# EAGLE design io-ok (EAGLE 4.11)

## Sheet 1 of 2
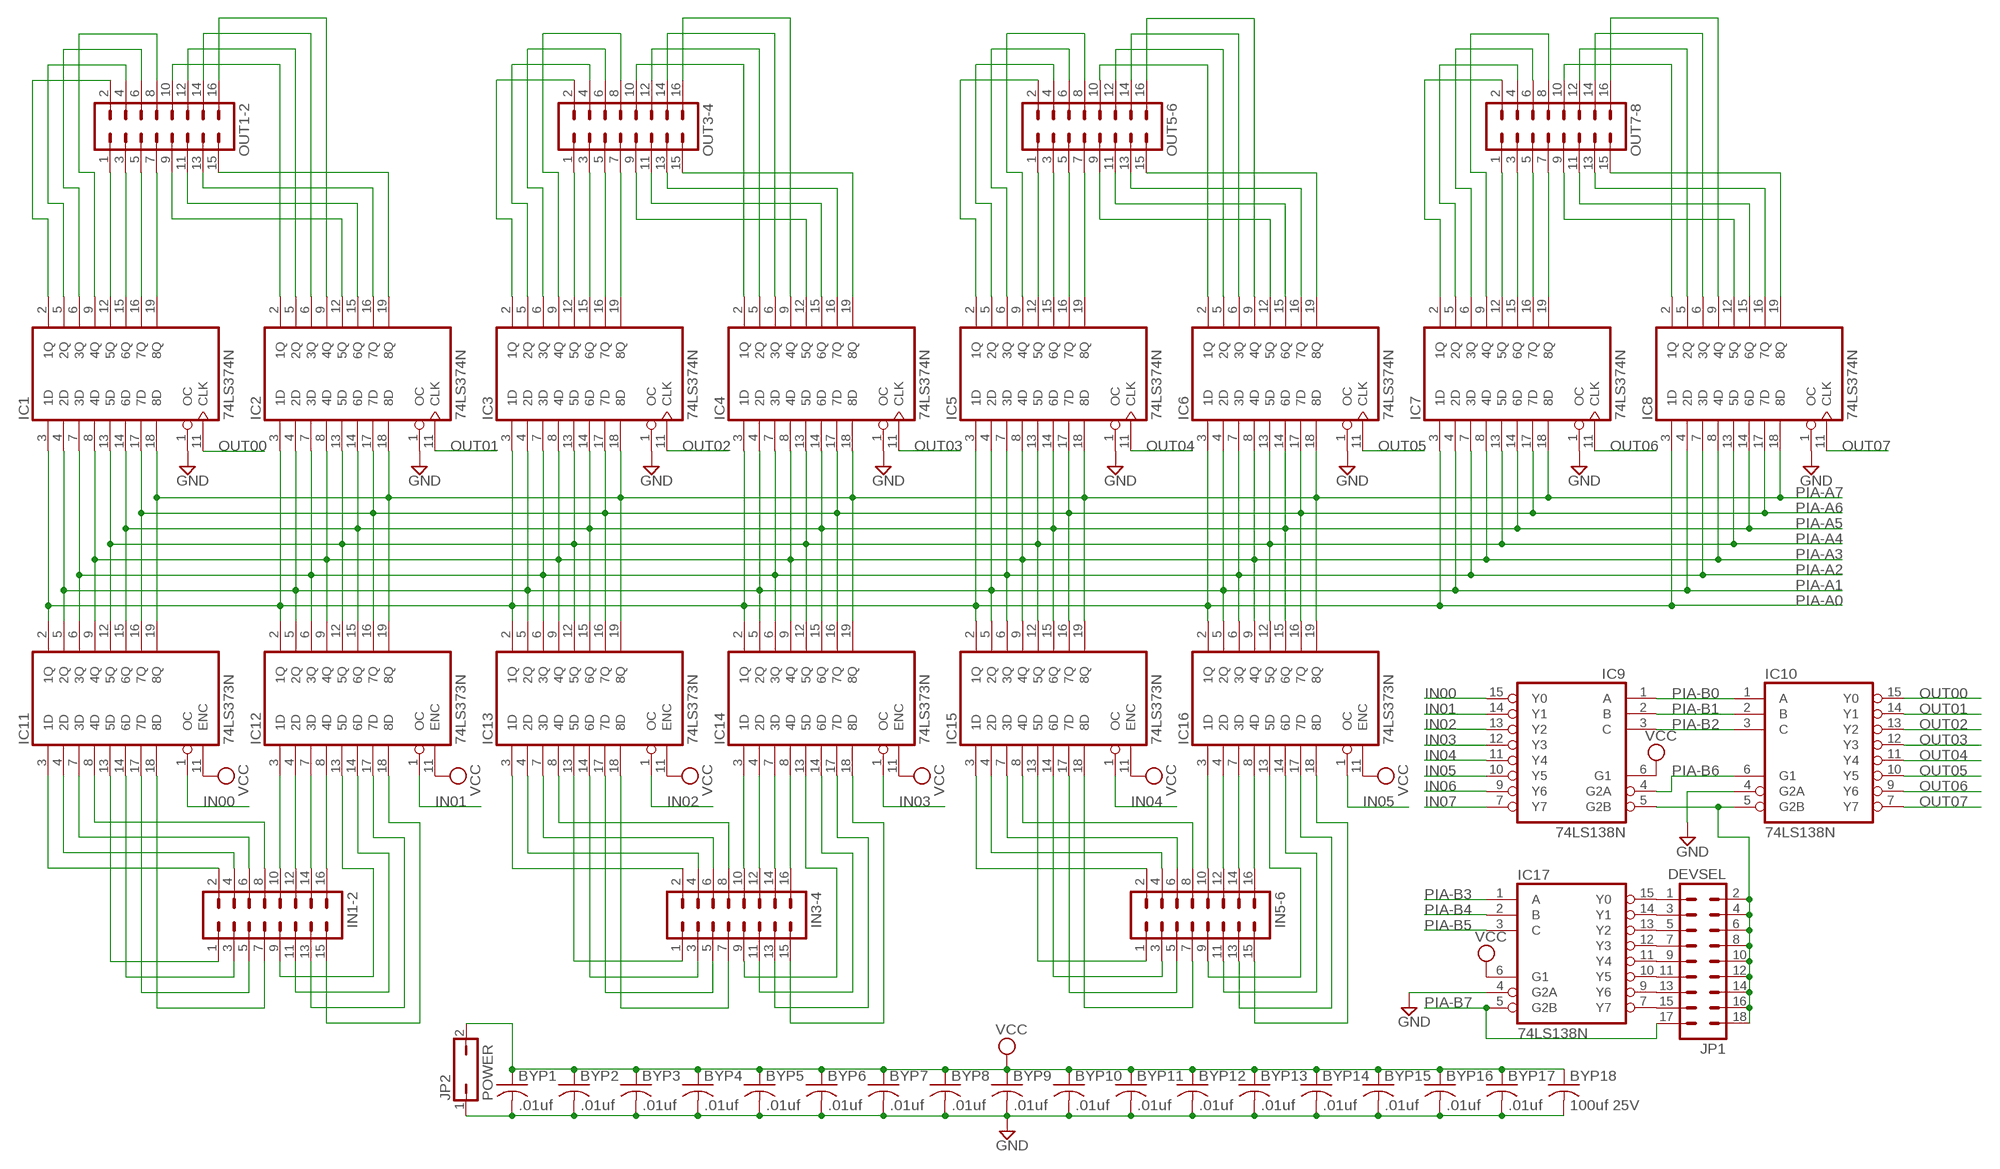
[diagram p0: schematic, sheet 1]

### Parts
BYP1  .01uf  C-US050-025X075  [C050-025X075]
BYP2  .01uf  C-US050-025X075  [C050-025X075]
BYP3  .01uf  C-US050-025X075  [C050-025X075]
BYP4  .01uf  C-US050-025X075  [C050-025X075]
BYP5  .01uf  C-US050-025X075  [C050-025X075]
BYP6  .01uf  C-US050-025X075  [C050-025X075]
BYP7  .01uf  C-US050-025X075  [C050-025X075]
BYP8  .01uf  C-US050-025X075  [C050-025X075]
BYP9  .01uf  C-US050-025X075  [C050-025X075]
BYP10  .01uf  C-US050-025X075  [C050-025X075]
BYP11  .01uf  C-US050-025X075  [C050-025X075]
BYP12  .01uf  C-US050-025X075  [C050-025X075]
BYP13  .01uf  C-US050-025X075  [C050-025X075]
BYP14  .01uf  C-US050-025X075  [C050-025X075]
BYP15  .01uf  C-US050-025X075  [C050-025X075]
BYP16  .01uf  C-US050-025X075  [C050-025X075]
BYP17  .01uf  C-US050-025X075  [C050-025X075]
BYP18  100uf 25V  C-US150-064X183  [C150-064X183]
IC1  74LS374N  [DIL20]
IC2  74LS374N  [DIL20]
IC3  74LS374N  [DIL20]
IC4  74LS374N  [DIL20]
IC5  74LS374N  [DIL20]
IC6  74LS374N  [DIL20]
IC7  74LS374N  [DIL20]
IC8  74LS374N  [DIL20]
IC9  74LS138N  [DIL16]
IC10  74LS138N  [DIL16]
IC11  74LS373N  [DIL20]
IC12  74LS373N  [DIL20]
IC13  74LS373N  [DIL20]
IC14  74LS373N  [DIL20]
IC15  74LS373N  [DIL20]
IC16  74LS373N  [DIL20]
IC17  74LS138N  [DIL16]
IN1-2  MA08-2  [MA08-2]
IN3-4  MA08-2  [MA08-2]
IN5-6  MA08-2  [MA08-2]
JP1  DEVSEL  MA09-2  [MA09-2]
JP2  POWER  JP1Q  [JP1]
OUT1-2  MA08-2  [MA08-2]
OUT3-4  MA08-2  [MA08-2]
OUT5-6  MA08-2  [MA08-2]
OUT7-8  MA08-2  [MA08-2]

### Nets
GND [Power]: BYP1.2 BYP2.2 BYP3.2 BYP4.2 BYP5.2 BYP6.2 BYP7.2 BYP8.2 BYP9.2 BYP10.2 BYP11.2 BYP12.2 BYP13.2 BYP14.2 BYP15.2 BYP16.2 BYP17.2 BYP18.2 IC1.1(OC) IC2.1(OC) IC3.1(OC) IC4.1(OC) IC5.1(OC) IC6.1(OC) IC7.1(OC) IC8.1(OC) IC10.4(G2A) IC17.4(G2A) JP2.1 ; also sheet 2
IN00: IC9.15(Y0) IC11.1(OC)
IN01: IC9.14(Y1) IC12.1(OC)
IN02: IC9.13(Y2) IC13.1(OC)
IN03: IC9.12(Y3) IC14.1(OC)
IN04: IC9.11(Y4) IC15.1(OC)
IN05: IC9.10(Y5) IC16.1(OC)
IN06: IC9.9(Y6)
IN07: IC9.7(Y7)
N$1: IC12.3(1D) IN1-2.10
N$2: IC12.4(2D) IN1-2.12
N$3: IC17.15(Y0) JP1.1
N$4: IC17.14(Y1) JP1.3
N$5: IC17.13(Y2) JP1.5
N$6: IC17.12(Y3) JP1.7
N$7: IC12.7(3D) IN1-2.14
N$8: IC12.8(4D) IN1-2.16
N$9: IC11.8(4D) IN1-2.8
N$10: IC11.7(3D) IN1-2.6
N$11: IC11.4(2D) IN1-2.4
N$12: IC11.3(1D) IN1-2.2
N$13: IC11.13(5D) IN1-2.1
N$14: IC11.14(6D) IN1-2.3
N$15: IC11.17(7D) IN1-2.5
N$16: IC11.18(8D) IN1-2.7
N$17: IC12.13(5D) IN1-2.9
N$18: IC12.14(6D) IN1-2.11
N$19: IC12.17(7D) IN1-2.13
N$20: IC12.18(8D) IN1-2.15
N$21: IC17.11(Y4) JP1.9
N$22: IC17.10(Y5) JP1.11
N$23: IC17.9(Y6) JP1.13
N$24: IC17.7(Y7) JP1.15
N$25: IC9.5(G2B) IC10.5(G2B) JP1.2 JP1.4 JP1.6 JP1.8 JP1.10 JP1.12 JP1.14 JP1.16 JP1.18
N$26: IC5.2(1Q) IC7.2(1Q) OUT5-6.2 OUT7-8.2
N$29: IC14.3(1D) IN3-4.10
N$30: IC14.4(2D) IN3-4.12
N$31: IC14.7(3D) IN3-4.14
N$32: IC14.8(4D) IN3-4.16
N$33: IC3.12(5Q) OUT3-4.1
N$34: IC3.15(6Q) OUT3-4.3
N$35: IC3.16(7Q) OUT3-4.5
N$36: IC3.19(8Q) OUT3-4.7
N$37: IC13.3(1D) IN3-4.2
N$38: IC13.4(2D) IN3-4.4
N$39: IC13.7(3D) IN3-4.6
N$40: IC13.8(4D) IN3-4.8
N$41: IC14.13(5D) IN3-4.9
N$42: IC14.14(6D) IN3-4.11
N$43: IC14.17(7D) IN3-4.13
N$44: IC14.18(8D) IN3-4.15
N$45: IC13.13(5D) IN3-4.1
N$46: IC13.14(6D) IN3-4.3
N$47: IC13.17(7D) IN3-4.5
N$48: IC13.18(8D) IN3-4.7
N$49: IC3.5(2Q) OUT3-4.4
N$50: IC3.6(3Q) OUT3-4.6
N$51: IC3.2(1Q) OUT3-4.2
N$52: IC3.9(4Q) OUT3-4.8
N$53: IC1.12(5Q) OUT1-2.1
N$54: IC1.15(6Q) OUT1-2.3
N$55: IC1.16(7Q) OUT1-2.5
N$56: IC1.19(8Q) OUT1-2.7
N$57: IC1.2(1Q) OUT1-2.2
N$58: IC1.5(2Q) OUT1-2.4
N$59: IC1.6(3Q) OUT1-2.6
N$60: IC1.9(4Q) OUT1-2.8
N$61: IC2.19(8Q) OUT1-2.15
N$62: IC2.16(7Q) OUT1-2.13
N$63: IC2.15(6Q) OUT1-2.11
N$64: IC2.12(5Q) OUT1-2.9
N$65: IC2.2(1Q) OUT1-2.10
N$66: IC2.5(2Q) OUT1-2.12
N$67: IC2.6(3Q) OUT1-2.14
N$68: IC2.9(4Q) OUT1-2.16
N$69: IC4.2(1Q) OUT3-4.10
N$70: IC4.5(2Q) OUT3-4.12
N$71: IC4.6(3Q) OUT3-4.14
N$72: IC4.9(4Q) OUT3-4.16
N$73: IC4.19(8Q) OUT3-4.15
N$74: IC4.16(7Q) OUT3-4.13
N$75: IC4.15(6Q) OUT3-4.11
N$76: IC4.12(5Q) OUT3-4.9
N$77: IC16.3(1D) IN5-6.10
N$78: IC16.4(2D) IN5-6.12
N$79: IC16.7(3D) IN5-6.14
N$80: IC16.8(4D) IN5-6.16
N$81: IC5.12(5Q) OUT5-6.1
N$82: IC5.15(6Q) OUT5-6.3
N$83: IC5.16(7Q) OUT5-6.5
N$84: IC5.19(8Q) OUT5-6.7
N$85: IC7.12(5Q) OUT7-8.1
N$86: IC7.15(6Q) OUT7-8.3
N$87: IC7.16(7Q) OUT7-8.5
N$88: IC7.19(8Q) OUT7-8.7
N$89: IC5.5(2Q) OUT5-6.4
N$90: IC5.6(3Q) OUT5-6.6
N$91: IC5.9(4Q) OUT5-6.8
N$92: IC6.12(5Q) OUT5-6.9
N$93: IC6.15(6Q) OUT5-6.11
N$95: IC6.16(7Q) OUT5-6.13
N$96: IC6.19(8Q) OUT5-6.15
N$97: IC6.2(1Q) OUT5-6.10
N$98: IC6.5(2Q) OUT5-6.12
N$99: IC6.6(3Q) OUT5-6.14
N$100: IC6.9(4Q) OUT5-6.16
N$101: IC15.3(1D) IN5-6.2
N$102: IC15.4(2D) IN5-6.4
N$103: IC15.7(3D) IN5-6.6
N$104: IC15.8(4D) IN5-6.8
N$105: IC16.13(5D) IN5-6.9
N$106: IC16.14(6D) IN5-6.11
N$107: IC16.17(7D) IN5-6.13
N$108: IC16.18(8D) IN5-6.15
N$109: IC15.13(5D) IN5-6.1
N$110: IC15.14(6D) IN5-6.3
N$111: IC15.17(7D) IN5-6.5
N$112: IC15.18(8D) IN5-6.7
N$113: IC8.19(8Q) OUT7-8.15
N$114: IC8.16(7Q) OUT7-8.13
N$115: IC8.15(6Q) OUT7-8.11
N$116: IC8.12(5Q) OUT7-8.9
N$117: IC8.2(1Q) OUT7-8.10
N$118: IC8.5(2Q) OUT7-8.12
N$119: IC8.6(3Q) OUT7-8.14
N$120: IC8.9(4Q) OUT7-8.16
N$121: IC7.9(4Q) OUT7-8.8
N$122: IC7.6(3Q) OUT7-8.6
N$123: IC7.5(2Q) OUT7-8.4
OUT00: IC1.11(CLK) IC10.15(Y0)
OUT01: IC2.11(CLK) IC10.14(Y1)
OUT02: IC3.11(CLK) IC10.13(Y2)
OUT03: IC4.11(CLK) IC10.12(Y3)
OUT04: IC5.11(CLK) IC10.11(Y4)
OUT05: IC6.11(CLK) IC10.10(Y5)
OUT06: IC7.11(CLK) IC10.9(Y6)
OUT07: IC8.11(CLK) IC10.7(Y7)
PIA-A0: IC1.3(1D) IC2.3(1D) IC3.3(1D) IC4.3(1D) IC5.3(1D) IC6.3(1D) IC7.3(1D) IC8.3(1D) IC11.2(1Q) IC12.2(1Q) IC13.2(1Q) IC14.2(1Q) IC15.2(1Q) IC16.2(1Q) ; also sheet 2
PIA-A1: IC1.4(2D) IC2.4(2D) IC3.4(2D) IC4.4(2D) IC5.4(2D) IC6.4(2D) IC7.4(2D) IC8.4(2D) IC11.5(2Q) IC12.5(2Q) IC13.5(2Q) IC14.5(2Q) IC15.5(2Q) IC16.5(2Q) ; also sheet 2
PIA-A2: IC1.7(3D) IC2.7(3D) IC3.7(3D) IC4.7(3D) IC5.7(3D) IC6.7(3D) IC7.7(3D) IC8.7(3D) IC11.6(3Q) IC12.6(3Q) IC13.6(3Q) IC14.6(3Q) IC15.6(3Q) IC16.6(3Q) ; also sheet 2
PIA-A3: IC1.8(4D) IC2.8(4D) IC3.8(4D) IC4.8(4D) IC5.8(4D) IC6.8(4D) IC7.8(4D) IC8.8(4D) IC11.9(4Q) IC12.9(4Q) IC13.9(4Q) IC14.9(4Q) IC15.9(4Q) IC16.9(4Q) ; also sheet 2
PIA-A4: IC1.13(5D) IC2.13(5D) IC3.13(5D) IC4.13(5D) IC5.13(5D) IC6.13(5D) IC7.13(5D) IC8.13(5D) IC11.12(5Q) IC12.12(5Q) IC13.12(5Q) IC14.12(5Q) IC15.12(5Q) IC16.12(5Q) ; also sheet 2
PIA-A5: IC1.14(6D) IC2.14(6D) IC3.14(6D) IC4.14(6D) IC5.14(6D) IC6.14(6D) IC7.14(6D) IC8.14(6D) IC11.15(6Q) IC12.15(6Q) IC13.15(6Q) IC14.15(6Q) IC15.15(6Q) IC16.15(6Q) ; also sheet 2
PIA-A6: IC1.17(7D) IC2.17(7D) IC3.17(7D) IC4.17(7D) IC5.17(7D) IC6.17(7D) IC7.17(7D) IC8.17(7D) IC11.16(7Q) IC12.16(7Q) IC13.16(7Q) IC14.16(7Q) IC15.16(7Q) IC16.16(7Q) ; also sheet 2
PIA-A7: IC1.18(8D) IC2.18(8D) IC3.18(8D) IC4.18(8D) IC5.18(8D) IC6.18(8D) IC7.18(8D) IC8.18(8D) IC11.19(8Q) IC12.19(8Q) IC13.19(8Q) IC14.19(8Q) IC15.19(8Q) IC16.19(8Q) ; also sheet 2
PIA-B0: IC9.1(A) IC10.1(A) ; also sheet 2
PIA-B1: IC9.2(B) IC10.2(B) ; also sheet 2
PIA-B2: IC9.3(C) IC10.3(C) ; also sheet 2
PIA-B3: IC17.1(A) ; also sheet 2
PIA-B4: IC17.2(B) ; also sheet 2
PIA-B5: IC17.3(C) ; also sheet 2
PIA-B6: IC9.4(G2A) IC10.6(G1) ; also sheet 2
PIA-B7: IC17.5(G2B) JP1.17 ; also sheet 2
VCC [Power]: BYP1.1 BYP2.1 BYP3.1 BYP4.1 BYP5.1 BYP6.1 BYP7.1 BYP8.1 BYP9.1 BYP10.1 BYP11.1 BYP12.1 BYP13.1 BYP14.1 BYP15.1 BYP16.1 BYP17.1 BYP18.1 IC9.6(G1) IC11.11(ENC) IC12.11(ENC) IC13.11(ENC) IC14.11(ENC) IC15.11(ENC) IC16.11(ENC) IC17.6(G1) JP2.2 ; also sheet 2

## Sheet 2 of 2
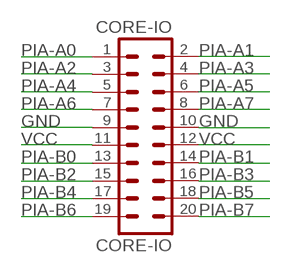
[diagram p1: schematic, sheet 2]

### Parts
CORE-IO  CORE-IO  MA10-2  [MA10-2]

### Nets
GND [Power]: CORE-IO.9 CORE-IO.10 ; also sheet 1
PIA-A0: CORE-IO.1 ; also sheet 1
PIA-A1: CORE-IO.2 ; also sheet 1
PIA-A2: CORE-IO.3 ; also sheet 1
PIA-A3: CORE-IO.4 ; also sheet 1
PIA-A4: CORE-IO.5 ; also sheet 1
PIA-A5: CORE-IO.6 ; also sheet 1
PIA-A6: CORE-IO.7 ; also sheet 1
PIA-A7: CORE-IO.8 ; also sheet 1
PIA-B0: CORE-IO.13 ; also sheet 1
PIA-B1: CORE-IO.14 ; also sheet 1
PIA-B2: CORE-IO.15 ; also sheet 1
PIA-B3: CORE-IO.16 ; also sheet 1
PIA-B4: CORE-IO.17 ; also sheet 1
PIA-B5: CORE-IO.18 ; also sheet 1
PIA-B6: CORE-IO.19 ; also sheet 1
PIA-B7: CORE-IO.20 ; also sheet 1
VCC [Power]: CORE-IO.11 CORE-IO.12 ; also sheet 1

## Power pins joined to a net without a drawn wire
GND: IC1.10(GND) IC2.10(GND) IC3.10(GND) IC4.10(GND) IC5.10(GND) IC6.10(GND) IC7.10(GND) IC8.10(GND) IC9.8(GND) IC10.8(GND) IC11.10(GND) IC12.10(GND) IC13.10(GND) IC14.10(GND) IC15.10(GND) IC16.10(GND) IC17.8(GND)
VCC: IC1.20(VCC) IC2.20(VCC) IC3.20(VCC) IC4.20(VCC) IC5.20(VCC) IC6.20(VCC) IC7.20(VCC) IC8.20(VCC) IC9.16(VCC) IC10.16(VCC) IC11.20(VCC) IC12.20(VCC) IC13.20(VCC) IC14.20(VCC) IC15.20(VCC) IC16.20(VCC) IC17.16(VCC)

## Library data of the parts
BYP1-BYP18 = rcl:C-US: CAPACITOR, American symbol
CORE-IO = con-lstb:MA10-2: PIN HEADER
IC1-IC8 = 74xx-us:74*374: Octal D type transparent LATCH, edge triggered
IC9 IC10 IC17 = 74xx-us:74*138: 3-line to 8-line DECODER/DEMULTIPLEXER
IC11-IC16 = 74xx-us:74*373: Octal D type transparent LATCH, edge triggered
IN1-2 IN3-4 IN5-6 OUT1-2 OUT3-4 OUT5-6 OUT7-8 = con-lstb:MA08-2: PIN HEADER
JP1 = con-lstb:MA09-2: PIN HEADER
JP2 = jumper:JP1Q: JUMPER

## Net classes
1 Power: width 0.508 mm, drill 0.254 mm, clearance 0.254 mm

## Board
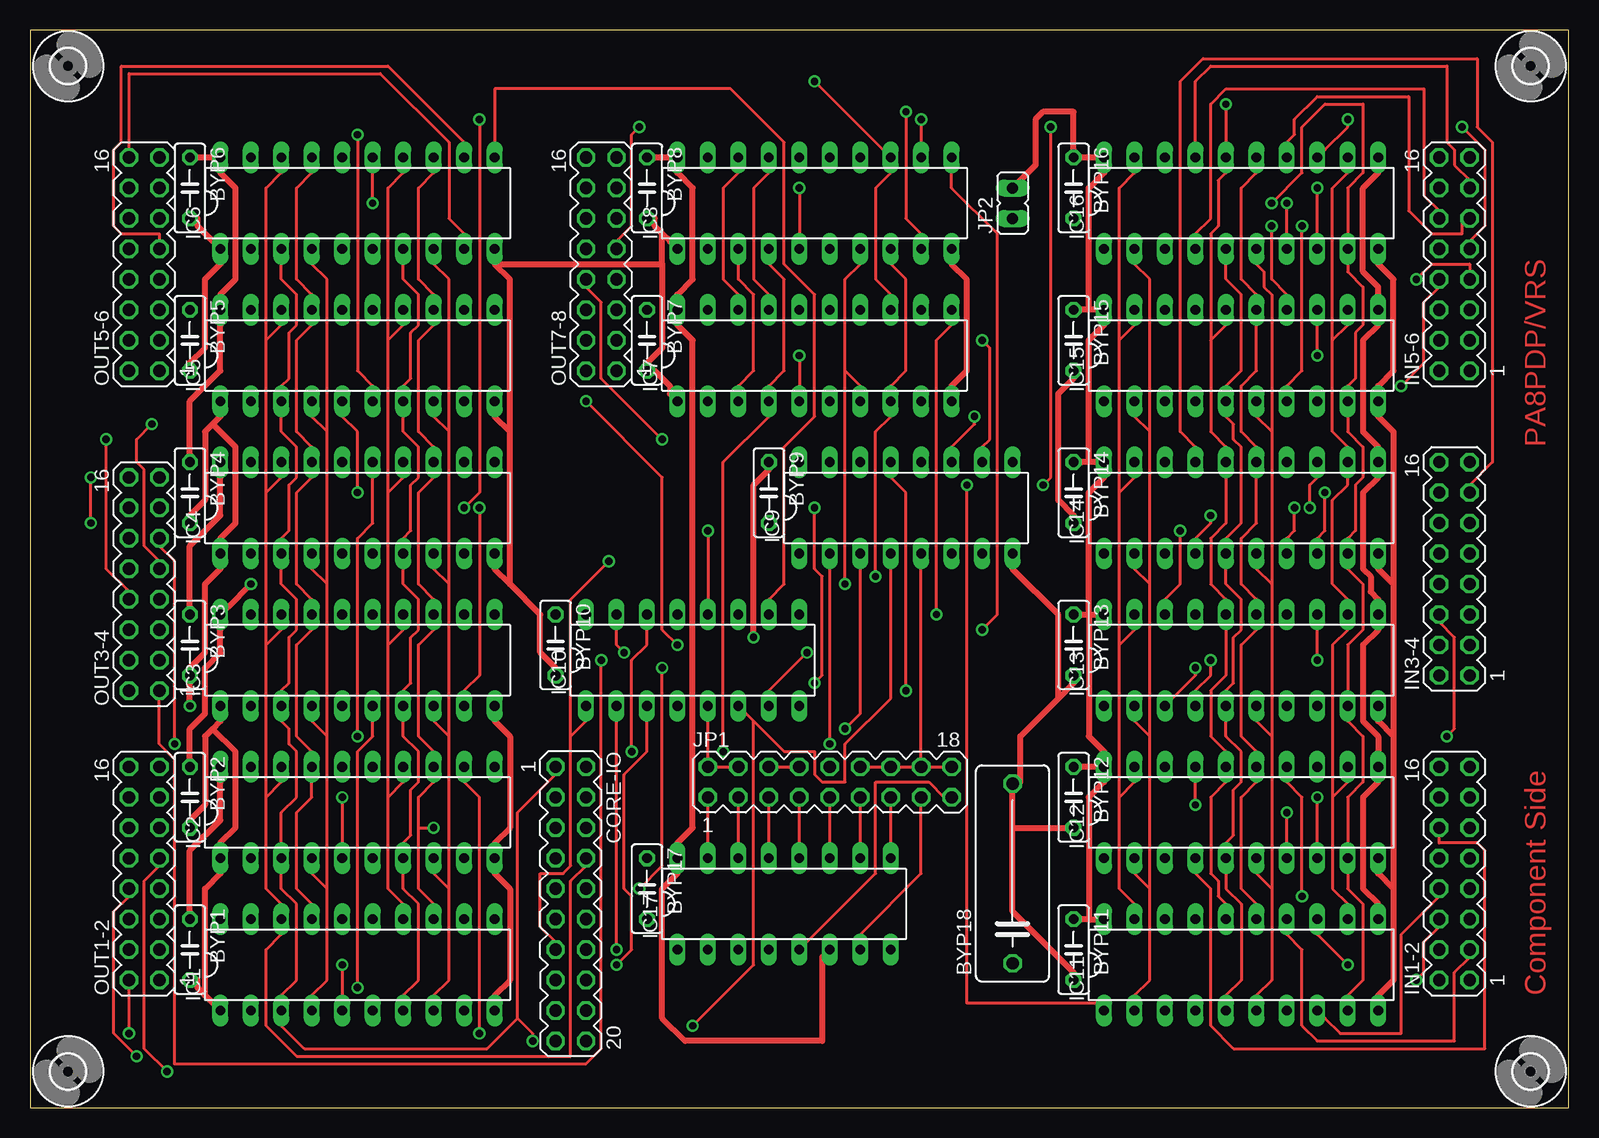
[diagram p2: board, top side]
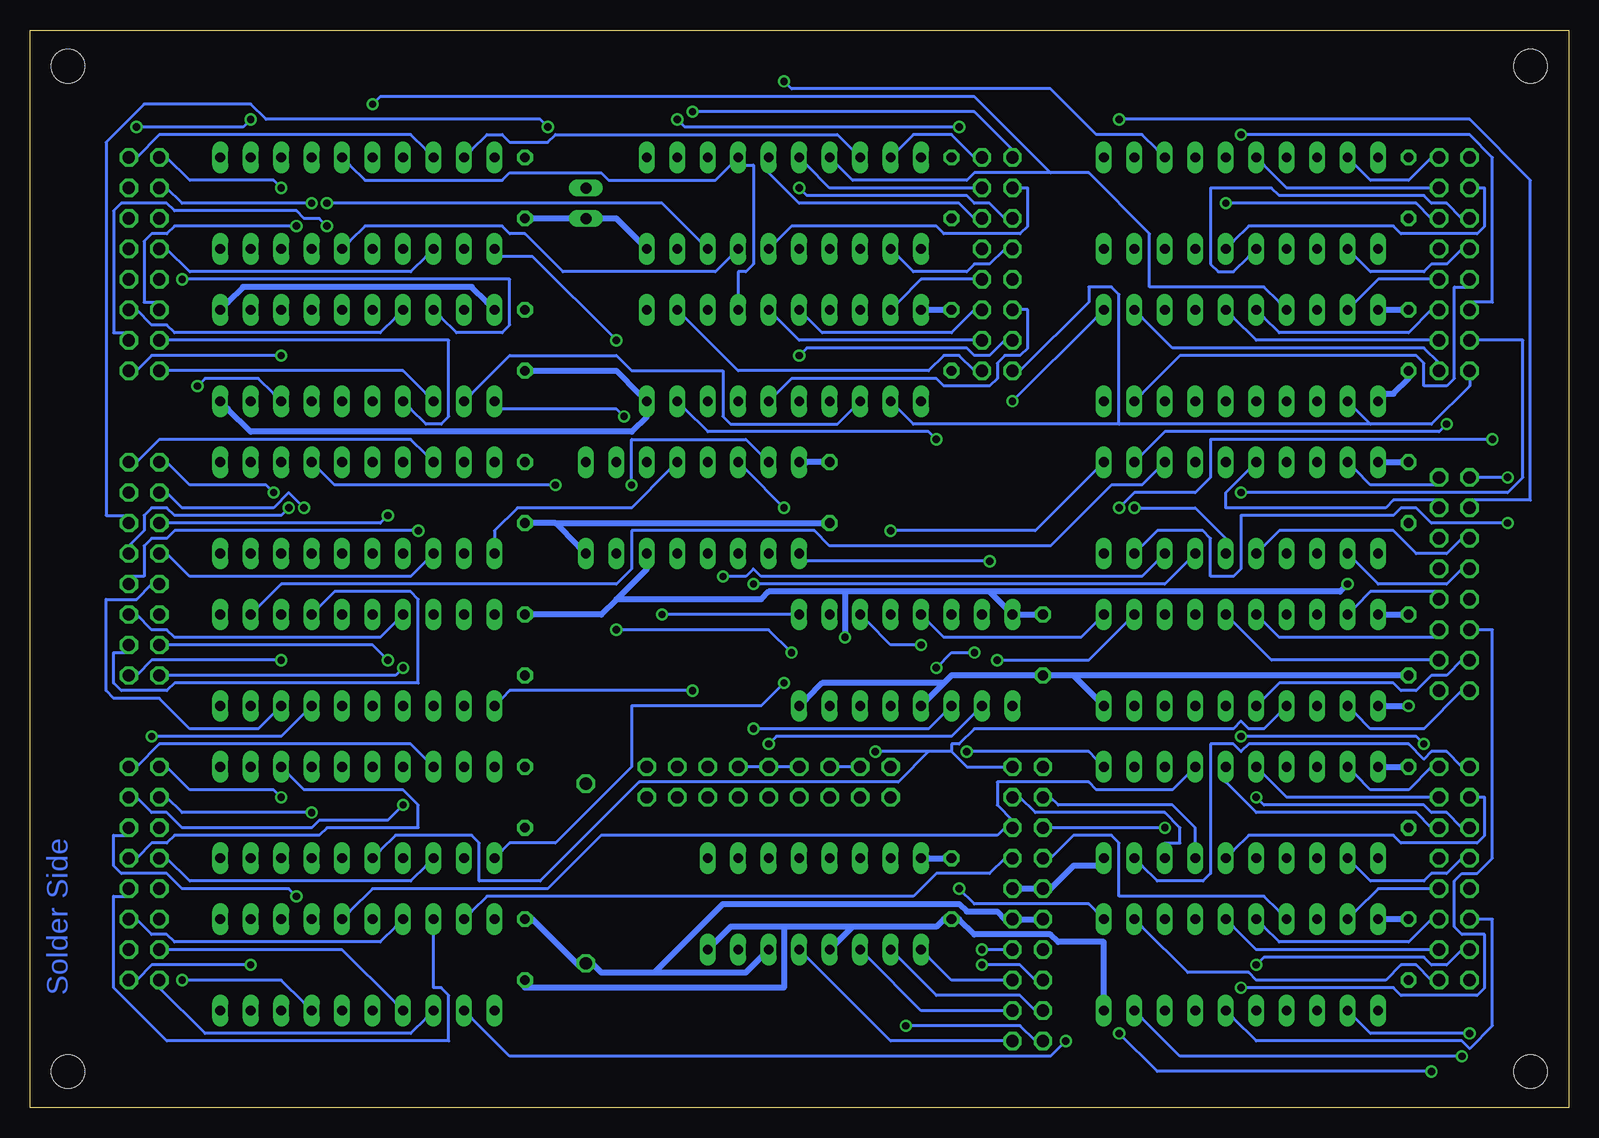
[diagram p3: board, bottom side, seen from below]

Size 128.25 x 89.84 mm. Coordinates in mm from the lower left corner, seen from the top.
Outline: 0,0 128.25,0 128.25,89.84 0,89.84 0,0
Copper layers (1*16): Top 0.035mm / dielectric 1.5mm / Bottom 0.035mm
Design rules "olimex10mil": minimum track width 10mil, minimum drill 24mil, track to track 10mil, track to pad 10mil, pad to pad 10mil, via to via 10mil, smd to smd 10mil, copper to edge 40mil, drill to drill 10mil, minimum pad ring 10mil, minimum via ring 8mil, stop-mask expansion 0mil, vias tented up to drill 0mil, thermal gap 10mil

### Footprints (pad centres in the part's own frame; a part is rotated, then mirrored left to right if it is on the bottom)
C050-025X075 = drill 0.813 octagon: 1 -2.54,0; 2 2.54,0
C150-064X183 = drill 1.016 octagon: 1 -7.493,0; 2 7.493,0
MA10-2 = drill 1.016 octagon: 1 -11.43,-1.27; 2 -11.43,1.27; 3 -8.89,-1.27; 4 -8.89,1.27; 5 -6.35,-1.27; 6 -6.35,1.27; 7 -3.81,-1.27; 8 -3.81,1.27; 9 -1.27,-1.27; 10 -1.27,1.27; 11 1.27,-1.27; 12 1.27,1.27; 13 3.81,-1.27; 14 3.81,1.27; 15 6.35,-1.27; 16 6.35,1.27; 17 8.89,-1.27; 18 8.89,1.27; 19 11.43,-1.27; 20 11.43,1.27
DIL20 = drill 0.813 long: 1 -11.43,-3.81; 2 -8.89,-3.81; 3 -6.35,-3.81; 4 -3.81,-3.81; 5 -1.27,-3.81; 6 1.27,-3.81; 7 3.81,-3.81; 8 6.35,-3.81; 9 8.89,-3.81; 10 11.43,-3.81; 11 11.43,3.81; 12 8.89,3.81; 13 6.35,3.81; 14 3.81,3.81; 15 1.27,3.81; 16 -1.27,3.81; 17 -3.81,3.81; 18 -6.35,3.81; 19 -8.89,3.81; 20 -11.43,3.81
DIL16 = drill 0.813 long: 1 -8.89,-3.81; 2 -6.35,-3.81; 3 -3.81,-3.81; 4 -1.27,-3.81; 5 1.27,-3.81; 6 3.81,-3.81; 7 6.35,-3.81; 8 8.89,-3.81; 9 8.89,3.81; 10 6.35,3.81; 11 3.81,3.81; 12 1.27,3.81; 13 -1.27,3.81; 14 -3.81,3.81; 15 -6.35,3.81; 16 -8.89,3.81
MA08-2 = drill 1.016 octagon: 1 -8.89,-1.27; 2 -8.89,1.27; 3 -6.35,-1.27; 4 -6.35,1.27; 5 -3.81,-1.27; 6 -3.81,1.27; 7 -1.27,-1.27; 8 -1.27,1.27; 9 1.27,-1.27; 10 1.27,1.27; 11 3.81,-1.27; 12 3.81,1.27; 13 6.35,-1.27; 14 6.35,1.27; 15 8.89,-1.27; 16 8.89,1.27
MA09-2 = drill 1.016 octagon: 1 -10.16,-1.27; 2 -10.16,1.27; 3 -7.62,-1.27; 4 -7.62,1.27; 5 -5.08,-1.27; 6 -5.08,1.27; 7 -2.54,-1.27; 8 -2.54,1.27; 9 0,-1.27; 10 0,1.27; 11 2.54,-1.27; 12 2.54,1.27; 13 5.08,-1.27; 14 5.08,1.27; 15 7.62,-1.27; 16 7.62,1.27; 17 10.16,-1.27; 18 10.16,1.27
JP1 = drill 0.914 long: 1 0,-1.27; 2 0,1.27
2,8 = hole 2.8: 0,0

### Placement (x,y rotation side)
BYP1  13.33,13.17 270 top
BYP2  13.33,25.87 270 top
BYP3  13.33,38.57 270 top
BYP4  13.33,51.27 270 top
BYP5  13.33,63.97 270 top
BYP6  13.33,76.67 270 top
BYP7  51.43,63.97 270 top
BYP8  51.43,76.67 270 top
BYP9  61.59,51.27 270 top
BYP10  43.81,38.57 270 top
BYP11  86.99,13.17 270 top
BYP12  86.99,25.87 270 top
BYP13  86.99,38.57 270 top
BYP14  86.99,51.27 270 top
BYP15  86.99,63.97 270 top
BYP16  86.99,76.67 270 top
BYP17  51.43,18.25 270 top
BYP18  81.91,19.52 90 top
CORE-IO  45.08,16.98 270 top
IC1  27.3,11.9 0 top
IC2  27.3,24.6 0 top
IC3  27.3,37.3 0 top
IC4  27.3,50 0 top
IC5  27.3,62.7 0 top
IC6  27.3,75.4 0 top
IC7  65.4,62.7 0 top
IC8  65.4,75.4 0 top
IC9  73.02,50 0 top
IC10  55.24,37.3 0 top
IC11  100.96,11.9 0 top
IC12  100.96,24.6 0 top
IC13  100.96,37.3 0 top
IC14  100.96,50 0 top
IC15  100.96,62.7 0 top
IC16  100.96,75.4 0 top
IC17  62.86,16.98 0 top
IN1-2  118.74,19.52 90 top
IN3-4  118.74,44.92 90 top
IN5-6  118.74,70.32 90 top
JP1  66.67,27.14 0 top
JP2  81.91,75.4 0 top
OUT1-2  9.52,19.52 90 top
OUT3-4  9.52,43.65 90 top
OUT5-6  9.52,70.32 90 top
OUT7-8  47.62,70.32 90 top
U$1  [2,8]  125.09,3.01 0 top
U$2  [2,8]  125.09,86.83 0 top
U$3  [2,8]  3.17,86.83 0 top
U$4  [2,8]  3.17,3.01 0 top

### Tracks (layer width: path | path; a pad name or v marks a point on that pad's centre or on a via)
GND  (via drill 0.61)
  Top 0.508: 15.24,31.58 15.87,32.22 IC3.1 | 15.24,31.58 14.6,30.95 14.6,25.23 13.33,23.96 BYP2.2 | 14.6,9.36 13.97,10 13.97,10.63 BYP1.2 | 14.6,9.36 15.24,8.73 IC1.1 | 14.6,9.36 14.6,18.25 15.87,19.52 IC2.1 15.87,22.06 17.14,23.33 17.14,29.68 15.24,31.58 | BYP6.2 13.97,74.13 13.97,73.5 15.24,72.22 IC6.1 15.87,70.32 14.6,69.05 14.6,63.34 13.33,62.06 BYP5.2 | 15.24,56.98 15.87,57.62 IC5.1 | 15.24,56.98 14.6,56.35 14.6,50.63 13.33,49.37 BYP4.2 | 15.24,56.98 17.14,55.08 17.14,48.73 15.87,47.46 IC4.1 15.87,44.92 14.6,43.65 14.6,37.94 13.33,36.66 BYP3.2 13.33,35.39 v13.33,33.49 | IC1.10 38.73,9.36 40,10.63 40,18.25 38.73,19.52 IC2.10 38.73,22.06 40,23.33 40,30.95 38.73,32.22 IC3.10 | IC7.1 53.34,59.52 53.34,60.16 52.07,61.43 BYP7.2 51.43,62.06 52.7,63.34 52.7,70.32 | 52.7,72.86 52.07,73.5 52.07,74.13 BYP8.2 | 52.7,72.86 53.34,72.22 IC8.1 | 52.7,70.32 52.7,72.86 | 40,43.65 42.54,41.11 42.54,37.94 43.81,36.66 BYP10.2 | 40,43.65 38.73,44.92 IC4.10 | 40,56.35 38.73,57.62 IC5.10 | 40,43.65 40,56.35 | 38.73,70.32 40,69.05 40,56.35 | 38.73,70.32 IC6.10 38.73,70.32 | 38.73,70.32 52.7,70.32 | 113.66,18.25 113.66,10.63 112.39,9.36 IC11.10 | 113.66,18.25 112.39,19.52 IC12.10 | 113.66,30.95 112.39,32.22 IC13.10 | 113.66,30.95 113.66,18.25 | 113.66,43.65 112.39,44.92 IC14.10 | 113.66,43.65 113.66,30.95 | 113.66,43.65 113.66,56.35 112.39,57.62 IC15.10 112.39,60.16 113.66,61.43 113.66,69.05 112.39,70.32 IC16.10 | IC7.10 76.83,60.16 78.1,61.43 78.1,69.05 76.83,70.32 IC8.10 | BYP15.2 86.99,60.8 85.72,59.52 85.72,50.63 86.99,49.37 BYP14.2 | 81.91,23.33 81.91,26.5 BYP18.2 82.55,27.14 82.55,30.95 85.72,34.12
  Top 0.508: 81.91,23.33 81.91,16.34 86.99,11.27 BYP11.2 | 81.91,23.33 86.35,23.33 BYP12.2 | 85.72,34.12 86.99,35.39 BYP13.2 | 85.72,34.12 85.72,41.11 81.91,44.92 IC9.8
  Bottom 0.508: BYP5.2 13.33,60.8 14.6,59.52 15.24,59.52 IC5.1 | v13.33,33.49 15.24,33.49 IC3.1 | CORE-IO.10 45.72,18.25 44.45,18.25 CORE-IO.9 43.18,18.25 41.27,20.15 39.37,20.15 IC2.10 | 41.27,36.03 39.37,34.12 IC3.10 | 41.27,36.03 43.18,36.03 BYP10.2 44.45,36.03 51.43,36.03 52.07,35.39 | 52.07,35.39 53.34,34.12 IC10.4 | 52.07,35.39 62.23,35.39 63.5,34.12 IC10.8 | 41.27,36.03 13.97,36.03 BYP3.2 | BYP15.2 86.35,61.43 79.37,61.43 77.46,59.52 IC7.10 76.83,57.62 78.1,56.35 109.85,56.35 111.75,58.25 IC15.10 | IC8.10 77.46,72.22 79.37,74.13 80.64,74.13 JP2.1 83.18,74.13 86.35,74.13 BYP16.2 | 84.45,48.73 82.55,46.82 IC9.8 | 84.45,48.73 86.35,48.73 BYP14.2 | 84.45,48.73 62.23,48.73 BYP9.2 | 59.69,15.08 52.7,15.08 52.07,15.71 BYP17.2 50.8,15.71 49.53,14.44 43.18,14.44 42.54,13.81 38.73,13.81 38.73,9.36 IC1.10 | 59.69,15.08 60.96,13.81 IC17.4 | 59.69,15.08 65.4,15.08 | 65.4,15.08 69.84,15.08 71.11,13.81 IC17.8 | 65.4,15.08 65.4,10 86.99,10 BYP11.2
IN00  (via drill 0.61)
  Top 0.254: v78.1,51.91 78.1,8.73 88.89,8.73 IC11.1
  Bottom 0.254: v78.1,51.91 78.1,55.71 68.57,55.71 67.3,54.45 IC9.15
IN01  (via drill 0.61)
  Top 0.254: v65.4,35.39 66.03,36.03 66.03,44.28 65.4,44.92 v65.4,50
  Bottom 0.254: v65.4,35.39 67.3,33.49 78.1,33.49 78.1,28.41 84.45,22.06 88.26,22.06 88.89,21.42 IC12.1 | v65.4,50 68.57,53.17 IC9.14
IN02  (via drill 0.61)
  Top 0.254: v73.02,34.76 73.02,51.27 71.75,52.54 IC9.13
  Bottom 0.254: v73.02,34.76 88.26,34.76 88.89,34.12 IC13.1
IN03
  Bottom 0.254: IC9.12 74.92,53.17 78.1,50 87.62,50 89.53,48.09 89.53,47.46 IC14.1
IN04  (via drill 0.61)
  Top 0.254: v78.73,57.62 78.73,56.98 76.83,55.08 IC9.11
  Bottom 0.254: v78.73,57.62 79.37,58.25 88.89,58.25 IC15.1
IN05  (via drill 0.61)
  Top 0.254: v79.37,63.97 80,63.34 80,55.71 79.37,55.08 IC9.10
  Bottom 0.254: v79.37,63.97 86.35,70.95 88.89,70.95 IC16.1
N$1
  Bottom 0.254: IC12.3 95.24,20.15 96.52,18.88 114.93,18.88 116.83,20.79 IN1-2.10
N$2
  Top 0.254: IC12.4 97.15,19.52 98.42,18.25 98.42,6.82 100.32,4.92 121.28,4.92 121.28,21.42 120.64,22.06 117.47,22.06 117.47,22.7 IN1-2.12
N$3
  Top 0.254: IC17.15 56.51,22.06 56.51,25.23 JP1.1
N$4
  Top 0.254: IC17.14 59.05,22.06 59.05,25.23 JP1.3
N$5
  Top 0.254: IC17.13 61.59,22.06 61.59,25.23 JP1.5
N$6
  Top 0.254: IC17.12 64.13,22.06 64.13,25.23 JP1.7
N$7  (via drill 0.61)
  Top 0.254: v104.77,24.6 104.77,22.06 IC12.7
  Bottom 0.254: v104.77,24.6 115.56,24.6 116.83,25.87 IN1-2.14
N$8  (via drill 0.61)
  Top 0.254: v107.31,25.87 107.31,22.06 IC12.8
  Bottom 0.254: v107.31,25.87 107.94,26.5 114.93,26.5 116.83,28.41 IN1-2.16
N$9
  Top 0.254: IC11.8 107.94,7.46 109.21,6.18 114.3,6.18 114.3,14.44 117.47,17.61 IN1-2.8
N$10  (via drill 0.61)
  Top 0.254: v115.56,10.63 116.2,11.27 116.2,13.81 117.47,15.08 IN1-2.6
  Bottom 0.254: v115.56,10.63 107.31,10.63 105.41,8.73 IC11.7
N$11
  Bottom 0.254: IC11.4 97.78,8.73 102.23,13.17 116.83,13.17 IN1-2.4
N$12
  Bottom 0.254: IC11.3 95.24,7.46 96.52,6.18 113.66,6.18 117.47,10 IN1-2.2
N$13  (via drill 0.61)
  Top 0.254: v109.85,11.9 107.31,14.44 IC11.13
  Bottom 0.254: v109.85,11.9 118.1,11.9 119.38,10.63 IN1-2.1
N$14
  Top 0.254: IC11.14 104.77,14.44 106.04,13.17 106.04,6.82 107.31,5.55 118.74,5.55 118.74,11.27 120.01,12.54 IN1-2.3
N$15
  Bottom 0.254: IC11.17 97.78,15.08 99.05,13.81 116.2,13.81 116.83,14.44 118.1,14.44 119.38,15.71 IN1-2.5
N$16
  Bottom 0.254: IC11.18 94.61,14.44 94.61,10 93.97,10 93.34,9.36 93.34,5.55 116.83,5.55 121.28,10 121.28,17.61 120.01,17.61 IN1-2.7
N$17
  Bottom 0.254: IC12.13 106.67,27.77 105.41,26.5 97.15,26.5 95.88,25.23 95.88,23.33 103.5,23.33 104.13,22.7 116.2,22.7 116.83,22.06 118.1,22.06 119.38,20.79 IN1-2.9
N$18  (via drill 0.61)
  Top 0.254: v106.04,17.61 106.04,25.87 104.77,27.14 IC12.14
  Bottom 0.254: v106.04,17.61 106.67,18.25 115.56,18.25 116.83,19.52 120.64,19.52 121.28,20.15 121.28,22.7 120.01,22.7 IN1-2.11
N$19  (via drill 0.61)
  Top 0.254: v97.15,25.23 97.15,27.14 IC12.17
  Bottom 0.254: v97.15,25.23 98.42,23.96 104.13,23.96 104.77,23.33 115.56,23.33 116.83,24.6 118.1,24.6 119.38,25.87 IN1-2.13
N$20
  Bottom 0.254: IC12.18 95.24,29.04 96.52,30.31 117.47,30.31 119.38,28.41 IN1-2.15
N$21
  Top 0.254: IC17.11 66.67,22.06 66.67,25.23 JP1.9
N$22
  Top 0.254: IC17.10 69.21,22.06 69.21,25.23 JP1.11
N$23
  Top 0.254: IC17.9 71.75,22.06 71.75,25.23 JP1.13
N$24
  Top 0.254: IC17.7 69.21,14.44 74.29,19.52 74.29,25.23 JP1.15
N$25
  Top 0.254: IC10.5 56.51,32.22 56.51,29.04 JP1.2 57.15,28.41 58.41,28.41 JP1.4 | JP1.8 63.5,28.41 62.23,28.41 JP1.6 | JP1.12 69.84,28.41 71.11,28.41 JP1.14 72.38,28.41 73.66,28.41 JP1.16 | IC9.5 74.29,44.92 74.29,29.04 JP1.16 | JP1.18 76.19,28.41 74.92,28.41 JP1.16
  Bottom 0.254: JP1.6 60.96,28.41 59.69,28.41 JP1.4 | JP1.8 64.77,28.41 66.03,28.41 JP1.10 67.3,28.41 68.57,28.41 JP1.12
N$26
  Bottom 0.254: 16.5,56.98 17.77,58.25 IC5.2 | 16.5,56.98 11.43,56.98 8.25,60.16 8.25,60.8 OUT5-6.2 | 16.5,56.98 37.46,56.98 | 37.46,56.98 54.61,56.98 55.88,58.25 IC7.2 | 37.46,56.98 37.46,67.78 38.1,68.41 40,68.41 40,67.14 45.72,61.43 OUT7-8.2
N$29
  Bottom 0.254: IC14.3 95.24,45.55 96.52,44.28 114.93,44.28 116.83,46.19 IN3-4.10
N$30  (via drill 0.61)
  Top 0.254: v98.42,49.37 98.42,48.73 97.15,47.46 IC14.4
  Bottom 0.254: v98.42,49.37 99.05,48.73 116.83,48.73 IN3-4.12
N$31  (via drill 0.61)
  Top 0.254: v105.41,50 105.41,48.09 104.77,47.46 IC14.7
  Bottom 0.254: v105.41,50 106.67,51.27 107.94,50 115.56,50 116.83,51.27 IN3-4.14
N$32  (via drill 0.61)
  Top 0.254: v107.94,51.27 107.94,48.09 107.31,47.46 IC14.8
  Bottom 0.254: v107.94,51.27 108.58,51.91 114.93,51.91 116.83,53.81 IN3-4.16
N$33  (via drill 0.61)
  Top 0.254: v47.62,37.3 47.62,4.92 46.35,3.64 12.06,3.64 12.06,29.04 10.79,30.31 10.79,34.12 OUT3-4.1
  Bottom 0.254: v47.62,37.3 40,37.3 36.83,40.48 IC3.12
N$34
  Bottom 0.254: IC3.15 27.93,40.48 24.76,37.3 11.43,37.3 OUT3-4.3
N$35
  Bottom 0.254: IC3.16 25.39,40.48 24.12,39.2 10.79,39.2 OUT3-4.5
N$36
  Bottom 0.254: IC3.19 17.77,41.74 16.5,43.02 10.79,43.02 OUT3-4.7
N$37  (via drill 0.61)
  Top 0.254: v97.15,36.66 97.15,36.03 95.24,34.12 IC13.3
  Bottom 0.254: v97.15,36.66 97.78,36.03 116.83,36.03 IN3-4.2
N$38  (via drill 0.61)
  Top 0.254: v98.42,37.3 98.42,36.03 97.15,34.76 IC13.4
  Bottom 0.254: v98.42,37.3 99.69,38.57 116.83,38.57 IN3-4.4
N$39  (via drill 0.61)
  Top 0.254: v118.1,30.95 118.74,31.58 118.74,39.2 117.47,40.48 IN3-4.6
  Bottom 0.254: v118.1,30.95 107.31,30.95 105.41,32.85 IC13.7
N$40
  Bottom 0.254: IC13.8 107.94,32.85 109.21,31.58 114.93,31.58 117.47,34.12 121.28,34.12 121.91,34.76 121.91,42.38 119.38,42.38 118.1,43.65 IN3-4.8
N$41  (via drill 0.61)
  Top 0.254: v106.67,50 106.67,51.91 107.31,52.54 IC14.13
  Bottom 0.254: v106.67,50 107.31,49.37 116.2,49.37 116.83,50 118.1,50 118.74,49.37 118.74,48.09 120.01,46.82 IN3-4.9
N$42  (via drill 0.61)
  Top 0.254: v84.45,51.91 85.08,52.54 v85.08,81.75
  Bottom 0.254: v84.45,51.91 102.86,51.91 104.13,53.17 IC14.14 | v85.08,81.75 85.72,82.39 108.58,82.39 109.85,83.66 118.74,83.66 121.91,80.48 121.91,49.37 120.01,49.37 IN3-4.11
N$43
  Top 0.254: IC14.17 97.15,55.08 95.88,56.35 95.88,85.56 97.78,87.47 120.64,87.47 120.64,81.75 121.91,80.48 121.91,53.81 120.01,51.91 IN3-4.13
N$44
  Bottom 0.254: IC14.18 95.24,54.45 96.52,55.71 117.47,55.71 119.38,53.81 IN3-4.15
N$45  (via drill 0.61)
  Top 0.254: v107.31,37.3 107.31,39.84 IC13.13
  Bottom 0.254: v107.31,37.3 118.1,37.3 119.38,36.03 IN3-4.1
N$46
  Bottom 0.254: IC13.14 104.13,41.74 102.86,43.02 96.52,43.02 95.88,42.38 95.88,35.39 116.2,35.39 116.83,34.76 120.64,34.76 121.28,35.39 121.28,37.94 120.01,37.94 IN3-4.3
N$47
  Bottom 0.254: IC13.17 97.78,40.48 99.05,39.2 116.2,39.2 116.83,39.84 118.1,39.84 119.38,41.11 IN3-4.5
N$48  (via drill 0.61)
  Top 0.254: v95.88,48.09 95.88,43.65 94.61,42.38 IC13.18
  Bottom 0.254: v95.88,48.09 116.2,48.09 116.83,47.46 118.1,47.46 118.74,46.82 118.74,44.28 120.01,44.28 IN3-4.7
N$49
  Bottom 0.254: IC3.5 25.39,34.12 24.12,35.39 14.6,35.39 13.97,34.76 12.7,34.76 11.43,36.03 10.16,36.03 8.89,37.3 OUT3-4.4
N$50  (via drill 0.61)
  Top 0.254: v27.3,10 27.3,29.68 28.57,30.95 28.57,32.22 IC3.6
  Bottom 0.254: v27.3,10 14.6,10 13.97,9.36 7.62,9.36 6.98,10 6.98,14.44 8.89,14.44 9.52,15.08 9.52,18.88 8.89,19.52 7.62,19.52 6.34,20.79 6.34,39.84 7.62,39.84 OUT3-4.6
N$51
  Bottom 0.254: IC3.2 17.77,32.85 16.5,31.58 12.06,31.58 8.89,34.76 OUT3-4.2
N$52  (via drill 0.61)
  Top 0.254: v37.46,50 37.46,36.03 36.19,34.76 IC3.9 | v6.34,55.71 6.34,44.92 8.25,43.02 OUT3-4.8
  Bottom 0.254: v37.46,50 36.19,51.27 31.11,51.27 29.84,52.54 29.84,55.71 v6.34,55.71
N$53
  Bottom 0.254: IC1.12 35.55,15.08 31.74,11.27 26.66,11.27 26.03,10.63 15.24,10.63 13.97,11.9 12.7,11.9 11.43,10.63 OUT1-2.1
N$54
  Bottom 0.254: IC1.15 27.93,15.08 26.03,13.17 11.43,13.17 OUT1-2.3
N$55
  Bottom 0.254: IC1.16 25.39,15.08 24.12,13.81 13.33,13.81 11.43,15.71 OUT1-2.5
N$56
  Bottom 0.254: IC1.19 17.77,16.34 15.87,18.25 11.43,18.25 OUT1-2.7
N$57  (via drill 0.61)
  Top 0.254: v8.25,6.18 8.25,10 OUT1-2.2
  Bottom 0.254: v8.25,6.18 16.5,6.18 17.77,7.46 IC1.2
N$58  (via drill 0.61)
  Top 0.254: v26.03,11.9 26.03,9.36 IC1.5
  Bottom 0.254: v26.03,11.9 25.39,12.54 12.06,12.54 11.43,11.9 10.16,11.9 8.89,13.17 OUT1-2.4
N$59
  Bottom 0.254: IC1.6 27.93,7.46 26.03,5.55 8.89,5.55 8.25,4.92 6.34,6.82 6.34,15.71 7.62,15.71 OUT1-2.6
N$60  (via drill 0.61)
  Top 0.254: v8.89,4.28 6.98,6.18 6.98,16.34 8.25,17.61 OUT1-2.8
  Bottom 0.254: v8.89,4.28 32.38,4.28 35.55,7.46 IC1.9
N$61
  Bottom 0.254: IC2.19 17.77,27.77 16.5,26.5 13.33,26.5 11.43,28.41 OUT1-2.15
N$62
  Bottom 0.254: IC2.16 25.39,27.77 23.49,25.87 11.43,25.87 OUT1-2.13
N$63
  Bottom 0.254: IC2.15 28.57,27.14 26.03,24.6 12.7,24.6 11.43,23.33 OUT1-2.11
N$64  (via drill 0.61)
  Top 0.254: v37.46,6.18 37.46,25.87 36.19,27.14 IC2.12 | v11.43,3.01 9.52,4.92 9.52,18.88 10.79,20.15 OUT1-2.9
  Bottom 0.254: v37.46,6.18 34.29,3.01 v11.43,3.01
N$65
  Bottom 0.254: IC2.2 17.77,20.15 16.5,18.88 12.06,18.88 11.43,19.52 10.16,19.52 8.89,20.79 OUT1-2.10
N$66  (via drill 0.61)
  Top 0.254: v26.03,25.87 26.03,22.06 IC2.5
  Bottom 0.254: v26.03,25.87 25.39,25.23 12.06,25.23 11.43,24.6 10.16,24.6 8.89,23.33 OUT1-2.12
N$67
  Bottom 0.254: IC2.6 27.93,21.42 26.66,22.7 14.6,22.7 13.97,22.06 7.62,22.06 6.98,22.7 6.98,25.87 7.62,25.87 OUT1-2.14
N$68
  Bottom 0.254: IC2.9 35.55,20.15 34.29,18.88 30.47,18.88 29.84,19.52 29.84,30.31 27.93,30.31 27.3,29.68 26.66,30.31 13.33,30.31 12.06,29.04 11.43,29.68 10.16,29.68 8.89,28.41 OUT1-2.16
N$69
  Bottom 0.254: IC4.2 17.77,45.55 15.87,43.65 10.16,43.65 8.89,44.92 OUT3-4.10
N$70
  Bottom 0.254: IC4.5 25.39,46.82 24.12,48.09 14.6,48.09 12.7,46.19 10.16,46.19 8.89,47.46 OUT3-4.12
N$71  (via drill 0.61)
  Top 0.254: v36.19,50 37.46,51.27 v37.46,82.39
  Bottom 0.254: v36.19,50 31.11,50 28.57,47.46 IC4.6 | v37.46,82.39 8.25,82.39 3.17,77.3 3.17,50.63 8.25,50.63 OUT3-4.14
N$72  (via drill 0.61)
  Top 0.254: v5.08,48.73 v5.08,52.54
  Bottom 0.254: v5.08,48.73 11.43,48.73 12.7,50 13.97,50 14.6,49.37 27.3,49.37 27.3,44.92 27.93,44.28 29.84,44.28 29.84,47.46 30.47,48.09 34.29,48.09 35.55,46.82 IC4.9 | v5.08,52.54 7.62,52.54 OUT3-4.16
N$73
  Bottom 0.254: IC4.19 17.77,53.17 16.5,51.91 10.79,51.91 OUT3-4.15
N$74
  Bottom 0.254: IC4.16 26.66,53.17 28.57,51.27 28.57,50 15.24,50 14.6,50.63 10.79,50.63 OUT3-4.13
N$75  (via drill 0.61)
  Top 0.254: v27.3,30.95 27.3,47.46 28.57,48.73 28.57,52.54 IC4.15 | v12.06,30.31 12.06,45.55 10.79,46.82 OUT3-4.11
  Bottom 0.254: v27.3,30.95 12.7,30.95 v12.06,30.31
N$76  (via drill 0.61)
  Top 0.254: v10.16,56.98 8.89,55.71 8.89,53.81 9.52,53.17 9.52,46.82 10.79,45.55 OUT3-4.9
  Bottom 0.254: v10.16,56.98 10.79,56.35 33.65,56.35 35.55,54.45 IC4.12
N$77
  Bottom 0.254: IC16.3 95.24,70.95 96.52,69.69 114.93,69.69 116.83,71.59 IN5-6.10
N$78
  Top 0.254: IC16.4 97.15,72.86 98.42,74.13 98.42,83.66 99.69,84.92 116.2,84.92 116.2,76.03 117.47,74.77 IN5-6.12
N$79  (via drill 0.61)
  Top 0.254: v104.77,75.4 104.77,72.86 IC16.7
  Bottom 0.254: v104.77,75.4 115.56,75.4 116.83,76.67 IN5-6.14
N$80  (via drill 0.61)
  Top 0.254: v107.31,76.67 107.31,72.86 IC16.8
  Bottom 0.254: v107.31,76.67 107.94,77.3 114.93,77.3 116.83,79.21 IN5-6.16
N$81
  Bottom 0.254: IC5.12 35.55,65.88 33.02,63.34 12.06,63.34 10.79,62.06 OUT5-6.1
N$82
  Bottom 0.254: IC5.15 27.93,65.88 26.03,63.97 11.43,63.97 OUT5-6.3
N$83
  Bottom 0.254: IC5.16 25.39,65.88 24.12,64.61 13.33,64.61 11.43,66.51 OUT5-6.5
N$84
  Bottom 0.254: IC5.19 17.77,67.14 15.87,69.05 11.43,69.05 OUT5-6.7
N$85
  Bottom 0.254: IC7.12 73.66,65.88 69.21,61.43 53.34,61.43 52.07,62.7 50.8,62.7 49.53,61.43 OUT7-8.1
N$86
  Bottom 0.254: IC7.15 66.03,65.88 64.13,63.97 49.53,63.97 OUT7-8.3
N$87
  Bottom 0.254: IC7.16 63.5,65.88 62.23,64.61 51.43,64.61 49.53,66.51 OUT7-8.5
N$88
  Bottom 0.254: IC7.19 55.88,67.14 53.97,69.05 49.53,69.05 OUT7-8.7
N$89  (via drill 0.61)
  Top 0.254: v27.3,51.27 27.3,56.35 26.03,57.62 IC5.5
  Bottom 0.254: v27.3,51.27 5.08,51.27 3.8,52.54 3.8,63.97 7.62,63.97 OUT5-6.4
N$90  (via drill 0.61)
  Top 0.254: v27.3,81.11 27.3,61.43 28.57,60.16 IC5.6
  Bottom 0.254: v27.3,81.11 8.25,81.11 6.34,79.21 6.34,67.14 8.25,67.14 OUT5-6.6
N$91
  Bottom 0.254: IC5.9 35.55,59.52 32.38,62.7 12.7,62.7 12.06,62.06 12.06,60.16 10.16,60.16 9.52,60.8 9.52,68.41 8.25,68.41 OUT5-6.8
N$92
  Top 0.254: IC6.12 36.19,80.48 29.84,86.83 7.62,86.83 7.62,80.48 6.98,79.84 6.98,73.5 7.62,72.86 10.79,72.86 10.79,72.22 OUT5-6.9
N$93  (via drill 0.61)
  Top 0.254: v28.57,75.4 28.57,77.94 IC6.15
  Bottom 0.254: v28.57,75.4 12.7,75.4 11.43,74.13 OUT5-6.11
N$95
  Bottom 0.254: IC6.16 25.39,78.58 23.49,76.67 11.43,76.67 OUT5-6.13
N$96
  Bottom 0.254: IC6.19 17.77,78.58 16.5,77.3 13.33,77.3 11.43,79.21 OUT5-6.15
N$97
  Bottom 0.254: IC6.2 17.77,70.95 16.5,69.69 12.06,69.69 11.43,70.32 10.16,70.32 8.89,71.59 OUT5-6.10
N$98
  Bottom 0.254: IC6.5 26.66,70.95 27.93,69.69 29.2,69.69 29.84,70.32 29.84,76.67 24.76,76.67 24.12,76.03 12.06,76.03 11.43,75.4 10.16,75.4 8.89,74.13 OUT5-6.12
N$99
  Bottom 0.254: IC6.6 27.93,72.22 26.66,73.5 14.6,73.5 13.97,72.86 7.62,72.86 6.98,73.5 6.98,76.67 7.62,76.67 OUT5-6.14
N$100
  Top 0.254: IC6.9 36.19,72.86 34.92,74.13 34.92,80.48 29.2,86.19 8.25,86.19 8.25,79.84 OUT5-6.16
N$101
  Bottom 0.254: IC15.3 95.24,59.52 97.15,61.43 116.83,61.43 IN5-6.2
N$102
  Bottom 0.254: IC15.4 96.52,58.25 95.24,56.98 93.97,56.98 93.34,57.62 93.34,63.97 116.83,63.97 IN5-6.4
N$103  (via drill 0.61)
  Top 0.254: v106.04,73.5 106.04,61.43 104.77,60.16 IC15.7
  Bottom 0.254: v106.04,73.5 116.2,73.5 116.83,72.86 118.1,72.86 118.74,72.22 118.74,67.14 117.47,67.14 IN5-6.6
N$104  (via drill 0.61)
  Top 0.254: v114.3,60.16 116.2,62.06 116.2,67.14 117.47,68.41 IN5-6.8
  Bottom 0.254: v114.3,60.16 113.66,60.8 109.21,60.8 107.94,59.52 IC15.8
N$105  (via drill 0.61)
  Top 0.254: v109.85,82.39 109.85,81.75 107.94,79.84 IC16.13 | v119.38,81.75 121.28,79.84 121.28,73.5 120.01,72.22 IN5-6.9
  Bottom 0.254: v109.85,82.39 110.48,81.75 v119.38,81.75
N$106
  Top 0.254: IC16.14 104.77,80.48 105.41,81.11 105.41,82.39 107.31,84.29 114.93,84.29 114.93,74.77 116.83,72.86 119.38,72.86 119.38,74.13 IN5-6.11
N$107
  Top 0.254: IC16.17 97.15,80.48 97.15,85.56 98.42,86.83 118.1,86.83 118.1,80.48 118.74,79.84 118.74,78.58 120.01,77.3 IN5-6.13
N$108
  Bottom 0.254: IC16.18 95.24,79.84 96.52,81.11 117.47,81.11 119.38,79.21 IN5-6.15
N$109  (via drill 0.61)
  Top 0.254: v107.31,62.7 107.31,65.24 IC15.13
  Bottom 0.254: v107.31,62.7 118.1,62.7 119.38,61.43 IN5-6.1
N$110  (via drill 0.61)
  Top 0.254: v103.5,73.5 103.5,69.05 104.77,67.78 IC15.14
  Bottom 0.254: v103.5,73.5 104.13,74.13 105.41,74.13 106.04,74.77 116.2,74.77 116.83,75.4 120.64,75.4 121.28,74.77 121.28,64.61 120.01,64.61 IN5-6.3
N$111
  Bottom 0.254: IC15.17 97.78,65.88 99.05,64.61 116.2,64.61 116.83,65.24 118.1,65.24 119.38,66.51 IN5-6.5
N$112  (via drill 0.61)
  Top 0.254: v115.56,69.05 116.83,70.32 120.01,70.32 120.01,69.69 IN5-6.7
  Bottom 0.254: v115.56,69.05 88.26,69.05 88.26,65.24 88.89,64.61 92.7,64.61 93.97,65.88 IC15.18
N$113
  Bottom 0.254: IC8.19 55.88,79.84 54.61,81.11 51.43,81.11 49.53,79.21 OUT7-8.15
N$114
  Bottom 0.254: IC8.16 63.5,78.58 61.59,76.67 49.53,76.67 OUT7-8.13
N$115
  Bottom 0.254: IC8.15 66.67,77.94 64.13,75.4 50.8,75.4 49.53,74.13 OUT7-8.11
N$116  (via drill 0.61)
  Top 0.254: v74.29,82.39 74.29,80.48 IC8.12 | v50.8,81.75 50.16,81.11 50.16,73.5 48.89,72.22 OUT7-8.9
  Bottom 0.254: v74.29,82.39 73.66,81.75 v50.8,81.75
N$117
  Bottom 0.254: IC8.2 55.88,70.95 54.61,69.69 50.16,69.69 49.53,70.32 48.26,70.32 46.98,71.59 OUT7-8.10
N$118  (via drill 0.61)
  Top 0.254: v64.13,76.67 64.13,72.86 IC8.5
  Bottom 0.254: v64.13,76.67 63.5,76.03 50.16,76.03 49.53,75.4 48.26,75.4 46.98,74.13 OUT7-8.12
N$119
  Bottom 0.254: IC8.6 66.03,72.22 64.77,73.5 52.7,73.5 52.07,72.86 45.72,72.86 45.08,73.5 45.08,76.67 45.72,76.67 OUT7-8.14
N$120  (via drill 0.61)
  Top 0.254: v73.02,83.02 73.02,74.13 74.29,72.86 IC8.9
  Bottom 0.254: v73.02,83.02 49.53,83.02 46.35,79.84 OUT7-8.16
N$121  (via drill 0.61)
  Top 0.254: v52.7,55.71 47.62,60.8 47.62,67.14 46.35,68.41 OUT7-8.8
  Bottom 0.254: v52.7,55.71 53.34,56.35 71.75,56.35 73.66,58.25 IC7.9
N$122
  Bottom 0.254: IC7.6 66.03,59.52 64.77,60.8 52.7,60.8 52.07,60.16 48.26,60.16 47.62,60.8 47.62,62.06 46.98,62.7 45.72,62.7 45.08,63.34 45.08,66.51 45.72,66.51 OUT7-8.6
N$123  (via drill 0.61)
  Top 0.254: v64.13,62.7 64.13,60.16 IC7.5
  Bottom 0.254: v64.13,62.7 63.5,63.34 50.16,63.34 49.53,62.7 48.26,62.7 46.98,63.97 OUT7-8.4
OUT00  (via drill 0.61)
  Top 0.254: v50.8,18.25 52.7,20.15 v52.7,36.66 | v49.53,37.94 48.89,38.57 48.89,39.84 IC10.15
  Bottom 0.254: v50.8,18.25 49.53,16.98 40,16.98 39.37,16.34 IC1.11 | v52.7,36.66 51.43,37.94 v49.53,37.94
OUT01  (via drill 0.61)
  Top 0.254: v50.16,29.68 50.16,37.3 51.43,38.57 51.43,39.84 IC10.14
  Bottom 0.254: v50.16,29.68 40,29.68 39.37,29.04 IC2.11
OUT02
  Bottom 0.254: IC3.11 39.37,40.48 40.64,39.2 52.07,39.2 53.34,40.48 IC10.13
OUT03  (via drill 0.61)
  Top 0.254: v56.51,48.09 56.51,42.38 IC10.12
  Bottom 0.254: v56.51,48.09 44.45,48.09 39.37,53.17 IC4.11
OUT04  (via drill 0.61)
  Top 0.254: v53.97,38.57 52.7,39.84 52.7,52.54 v46.35,58.89
  Bottom 0.254: v53.97,38.57 56.51,38.57 58.41,40.48 IC10.11 | v46.35,58.89 39.37,65.88 IC5.11
OUT05
  Top 0.254: IC10.10 61.59,42.38 62.86,43.65 62.86,55.08 65.4,57.62 65.4,67.78 62.86,70.32 62.86,80.48 58.41,84.92 38.73,84.92 38.73,80.48 IC6.11
OUT06  (via drill 0.61)
  Top 0.254: v75.56,41.11 75.56,63.97 76.83,65.24 IC7.11
  Bottom 0.254: v75.56,41.11 64.77,41.11 IC10.9
OUT07  (via drill 0.61)
  Top 0.254: v64.77,37.94 61.59,34.76 IC10.7 | v79.37,39.84 80.64,41.11 80.64,72.86 76.83,76.67 76.83,77.94 IC8.11
  Bottom 0.254: v64.77,37.94 66.67,39.84 v79.37,39.84
PIA-A0  (via drill 0.61)
  Top 0.254: IC6.3 20.95,70.32 20.95,69.05 22.22,67.78 22.22,65.24 21.58,64.61 21.58,60.8 20.95,60.16 IC5.3 20.95,57.62 20.95,56.35 22.22,55.08 22.22,52.54 21.58,51.91 21.58,48.09 20.95,47.46 IC4.3 20.95,44.92 20.95,43.65 22.22,42.38 22.22,39.84 21.58,39.2 21.58,35.39 20.95,34.76 IC3.3 20.95,32.22 21.58,31.58 21.58,30.31 22.22,29.68 22.22,25.87 20.95,24.6 20.95,22.06 IC2.3 20.95,19.52 20.95,18.25 22.22,16.98 22.22,10.63 20.95,9.36 IC1.3 20.95,6.82 22.86,4.92 38.1,4.92 40.64,7.46 | 40.64,7.46 40.64,24.6 43.81,27.77 CORE-IO.1 | IC7.3 59.05,60.16 60.32,61.43 60.32,67.78 59.05,69.05 59.05,70.32 IC8.3 | 93.34,18.25 93.34,10.63 92.07,9.36 IC11.2 | 93.34,18.25 92.07,19.52 IC12.2 | 93.34,30.95 92.07,32.22 IC13.2 | 93.34,18.25 93.34,30.95 | 93.34,43.65 92.07,44.92 IC14.2 | 93.34,30.95 93.34,43.65 | 93.34,56.35 92.07,57.62 IC15.2 | 93.34,43.65 93.34,56.35 | 93.34,56.35 93.34,69.05 92.07,70.32 IC16.2 | 40.64,7.46 41.91,6.18 v41.91,5.55
  Bottom 0.254: IC7.3 59.69,58.25 60.96,56.98 69.84,56.98 70.48,57.62 70.48,61.43 78.1,61.43 79.37,62.7 88.26,62.7 91.44,59.52 IC15.2 | v41.91,5.55 43.18,4.28 88.26,4.28 91.44,7.46 IC11.2
PIA-A1  (via drill 0.61)
  Top 0.254: IC16.5 99.69,70.32 99.69,69.05 100.96,67.78 100.96,61.43 99.69,60.16 IC15.5 99.69,57.62 100.32,56.98 100.32,55.71 100.96,55.08 100.96,48.73 99.69,47.46 IC14.5 99.69,44.92 99.69,43.65 100.96,42.38 100.96,39.84 100.32,39.2 100.32,35.39 99.69,34.76 IC13.5 99.69,32.22 99.69,30.95 100.96,29.68 100.96,27.14 100.32,26.5 100.32,22.7 99.69,22.06 IC12.5 99.69,19.52 99.69,18.25 100.96,16.98 100.96,10.63 99.69,9.36 IC11.5 | IC8.4 61.59,70.32 62.86,69.05 62.86,61.43 61.59,60.16 IC7.4 61.59,57.62 57.78,53.81 v57.78,29.68 | 24.76,18.25 24.76,10.63 23.49,9.36 IC1.4 | 24.76,18.25 23.49,19.52 IC2.4 | 24.76,30.95 23.49,32.22 IC3.4 | 24.76,18.25 24.76,30.95 | 24.76,43.65 23.49,44.92 IC4.4 | 24.76,30.95 24.76,43.65 | 24.76,56.35 23.49,57.62 IC5.4 | 24.76,43.65 24.76,56.35 | 24.76,56.35 24.76,69.05 23.49,70.32 IC6.4
  Bottom 0.254: 51.43,29.68 50.16,28.41 46.98,28.41 CORE-IO.2 | 51.43,29.68 51.43,30.31 50.8,30.31 49.53,31.58 27.93,31.58 27.3,32.22 26.66,31.58 25.39,31.58 24.12,32.85 IC3.4 | 51.43,29.68 53.34,29.68 | 53.34,29.68 v57.78,29.68 | 53.34,29.68 55.88,27.14 77.46,27.14 85.72,18.88 90.8,18.88 90.8,22.06 91.44,22.7 97.78,22.7 99.05,21.42 IC12.5
PIA-A2  (via drill 0.61)
  Top 0.254: IC1.7 31.11,9.36 32.38,10.63 32.38,16.98 31.11,18.25 31.11,19.52 IC2.7 31.11,22.06 31.74,22.7 31.74,26.5 32.38,27.14 32.38,29.68 31.11,30.95 31.11,32.22 IC3.7 31.11,34.76 31.74,35.39 31.74,39.2 32.38,39.84 32.38,42.38 31.11,43.65 31.11,44.92 IC4.7 31.11,47.46 31.74,48.09 31.74,51.91 32.38,52.54 32.38,55.08 31.11,56.35 31.11,57.62 IC5.7 31.11,60.16 31.74,60.8 31.74,64.61 32.38,65.24 32.38,67.78 31.11,69.05 31.11,70.32 IC6.7 | 67.94,61.43 69.21,60.16 IC7.7 | 67.94,61.43 67.94,69.05 69.21,70.32 IC8.7 | 103.5,18.25 103.5,10.63 102.23,9.36 IC11.6 | 103.5,18.25 102.23,19.52 IC12.6 | 103.5,30.95 102.23,32.22 IC13.6 | 103.5,30.95 103.5,18.25 | 103.5,43.65 102.23,44.92 IC14.6 | 103.5,43.65 103.5,30.95 | 103.5,56.35 102.23,57.62 IC15.6 | 103.5,56.35 103.5,43.65 | 103.5,56.35 103.5,67.78 102.86,68.41 102.86,69.69 102.23,70.32 IC16.6 | v67.94,43.65 67.94,61.43
  Bottom 0.254: CORE-IO.3 43.18,25.87 42.54,25.23 33.02,25.23 31.11,23.33 31.11,22.06 IC2.7 | IC8.7 69.84,70.95 71.11,69.69 83.81,69.69 86.99,72.86 88.26,72.86 88.89,73.5 100.32,73.5 101.59,72.22 IC16.6 | v67.94,43.65 33.65,43.65 31.74,45.55 IC4.7
PIA-A3  (via drill 0.61)
  Top 0.254: 34.92,18.25 34.92,10.63 33.65,9.36 IC1.8 | 34.92,18.25 33.65,19.52 IC2.8 | 34.92,30.95 33.65,32.22 IC3.8 | 34.92,18.25 34.92,30.95 | 34.92,43.65 33.65,44.92 IC4.8 | 34.92,30.95 34.92,43.65 | 34.92,56.35 33.65,57.62 IC5.8 | 34.92,43.65 34.92,56.35 | 34.92,56.35 34.92,69.05 33.65,70.32 IC6.8 | IC11.9 109.85,9.36 111.12,10.63 111.12,16.98 109.85,18.25 109.85,19.52 IC12.9 109.85,22.06 109.85,25.87 111.12,27.14 111.12,30.95 109.85,32.22 IC13.9 109.85,34.76 109.85,38.57 111.12,39.84 111.12,43.65 109.85,44.92 IC14.9 109.85,47.46 110.48,48.09 110.48,51.91 111.12,52.54 111.12,55.08 109.85,56.35 109.85,57.62 IC15.9 109.85,60.16 110.48,60.8 110.48,64.61 111.12,65.24 111.12,68.41 109.85,69.69 109.85,70.32 IC16.9 109.85,72.86 109.85,76.67 111.12,77.94 111.12,83.66 107.94,83.66 106.04,81.75 106.04,77.94 v103.5,75.4 | IC8.8 71.75,70.32 73.02,69.05 73.02,61.43 71.75,60.16 IC7.8 71.75,57.62 70.48,56.35 v70.48,44.28
  Bottom 0.254: CORE-IO.4 45.72,25.87 44.45,24.6 33.65,24.6 32.38,23.33 32.38,22.06 33.65,22.06 IC2.8 | v103.5,75.4 75.56,75.4 72.38,72.22 IC8.8 | v70.48,44.28 68.57,44.28 67.94,44.92 67.3,44.28 35.55,44.28 34.29,45.55 IC4.8
PIA-A4  (via drill 0.61)
  Top 0.254: 108.58,25.87 108.58,18.25 109.85,16.98 IC11.12 | 108.58,25.87 109.85,27.14 IC12.12 | 108.58,25.87 108.58,38.57 109.85,39.84 IC13.12 109.85,42.38 108.58,43.65 108.58,50.63 109.85,51.91 109.85,52.54 IC14.12 109.85,55.08 108.58,56.35 108.58,63.97 | 108.58,63.97 109.85,65.24 IC15.12 | 108.58,63.97 108.58,76.67 109.85,77.94 IC16.12 | IC7.13 71.75,67.78 70.48,69.05 70.48,76.67 71.75,77.94 IC8.13 71.11,79.84 v65.4,85.56 | 32.38,23.33 32.38,25.87 33.65,27.14 IC2.13 33.65,29.68 32.38,30.95 32.38,38.57 33.65,39.84 IC3.13 33.65,42.38 32.38,43.65 32.38,51.27 33.65,52.54 IC4.13 33.65,55.08 32.38,56.35 32.38,63.97 33.65,65.24 IC5.13 33.65,67.78 32.38,69.05 32.38,76.67 33.65,77.94 IC6.13 | 32.38,23.33 32.38,18.25 33.65,16.98 IC1.13 | 32.38,23.33 v33.65,23.33
  Bottom 0.254: v33.65,23.33 43.18,23.33 CORE-IO.5 | v65.4,85.56 64.77,84.92 43.18,84.92 39.37,81.11 35.55,81.11 34.29,79.84 IC6.13 | IC13.12 109.21,41.74 107.31,43.65 79.37,43.65 78.1,44.92 78.1,48.09 62.86,48.09 61.59,46.82 43.18,46.82 38.1,51.91 35.55,51.91 34.29,53.17 IC4.13
PIA-A5
  Top 0.254: 29.84,25.87 29.84,18.25 31.11,16.98 IC1.14 | 29.84,25.87 31.11,27.14 IC2.14 | 29.84,38.57 31.11,39.84 IC3.14 | 29.84,25.87 29.84,38.57 | 29.84,51.27 31.11,52.54 IC4.14 | 29.84,38.57 29.84,51.27 | 29.84,63.97 31.11,65.24 IC5.14 | 29.84,51.27 29.84,63.97 | 29.84,63.97 29.84,76.67 31.11,77.94 IC6.14 | IC11.15 102.23,16.98 100.96,18.25 100.96,25.87 102.23,27.14 IC12.15 102.23,29.68 100.96,30.95 100.96,38.57 102.23,39.84 IC13.15 102.23,42.38 100.96,43.65 100.96,47.46 102.23,48.73 102.23,52.54 IC14.15 102.23,55.08 100.96,56.35 100.96,60.16 102.23,61.43 102.23,65.24 IC15.15 102.23,67.78 100.96,69.05 100.96,76.67 102.23,77.94 IC16.15
  Bottom 0.254: IC2.14 31.74,27.77 33.02,26.5 39.37,26.5 40,27.14 47.62,27.14 47.62,25.23 46.35,23.96 CORE-IO.6 46.98,23.33 47.62,22.7 80.64,22.7 85.08,18.25 99.69,18.25 101.59,16.34 IC11.15 | IC7.14 69.21,67.78 69.21,69.69 68.57,69.69 67.94,70.32 67.94,78.58 68.57,78.58 IC8.14 69.84,78.58 71.11,77.3 80,77.3 80.64,77.94 88.26,77.94 88.89,77.3 100.32,77.3 101.59,78.58 IC16.15
PIA-A6  (via drill 0.61)
  Top 0.254: IC11.16 99.69,16.98 99.05,17.61 99.05,18.88 98.42,19.52 98.42,25.87 99.69,27.14 IC12.16 99.69,29.68 98.42,30.95 98.42,34.76 99.69,36.03 99.69,39.84 IC13.16 99.69,42.38 98.42,43.65 98.42,47.46 99.69,48.73 99.69,52.54 IC14.16 99.69,55.08 98.42,56.35 98.42,63.97 | 98.42,63.97 99.69,65.24 IC15.16 | 98.42,63.97 98.42,72.86 99.05,73.5 99.05,77.3 99.69,77.94 IC16.16 99.69,80.48 v99.69,83.66 | IC7.17 61.59,67.78 60.32,69.05 60.32,76.67 61.59,77.94 IC8.17 | IC1.17 23.49,16.98 22.22,18.25 22.22,24.6 23.49,25.87 23.49,27.14 IC2.17 23.49,29.68 22.22,30.95 22.22,38.57 23.49,39.84 IC3.17 23.49,42.38 22.22,43.65 22.22,51.27 23.49,52.54 IC4.17 23.49,55.08 22.22,56.35 22.22,63.97 23.49,65.24 IC5.17 23.49,67.78 22.22,69.05 22.22,76.67 23.49,77.94 IC6.17
  Bottom 0.254: CORE-IO.7 43.18,20.79 41.27,22.7 38.1,22.7 37.46,22.06 37.46,17.61 25.39,17.61 24.12,16.34 IC1.17 | 43.18,77.94 40,77.94 34.92,72.86 34.92,68.41 25.39,68.41 24.12,67.14 IC5.17 | 43.18,77.94 49.53,77.94 50.16,77.3 59.69,77.3 60.96,78.58 IC8.17 | v99.69,83.66 99.05,84.29 49.53,84.29 43.18,77.94
PIA-A7
  Top 0.254: 19.68,25.87 19.68,18.25 20.95,16.98 IC1.18 20.95,14.44 19.68,13.17 19.68,6.82 22.22,4.28 45.08,4.28 45.08,18.88 46.35,20.15 CORE-IO.8 | 19.68,25.87 20.95,27.14 IC2.18 | 19.68,38.57 20.95,39.84 IC3.18 | 19.68,25.87 19.68,38.57 | 19.68,51.27 20.95,52.54 IC4.18 | 19.68,38.57 19.68,51.27 | 19.68,63.97 20.95,65.24 IC5.18 | 19.68,51.27 19.68,63.97 | 19.68,63.97 19.68,76.67 20.95,77.94 IC6.18 | IC7.18 59.05,67.78 57.78,69.05 57.78,76.67 59.05,77.94 IC8.18 | 90.8,25.87 90.8,18.25 92.07,16.98 IC11.19 | 90.8,25.87 92.07,27.14 IC12.19 | 90.8,38.57 92.07,39.84 IC13.19 | 90.8,25.87 90.8,38.57 | 90.8,51.27 92.07,52.54 IC14.19 | 90.8,38.57 90.8,51.27 | 90.8,63.97 92.07,65.24 IC15.19 | 90.8,51.27 90.8,63.97 | 90.8,63.97 90.8,76.67 92.07,77.94 IC16.19
  Bottom 0.254: CORE-IO.8 46.98,20.79 48.26,19.52 52.7,19.52 54.61,17.61 90.16,17.61 91.44,16.34 IC11.19 | IC8.18 59.69,79.84 60.96,81.11 84.45,81.11 85.08,80.48 88.26,80.48 88.89,81.11 90.16,81.11 91.44,79.84 IC16.19
PIA-B0  (via drill 0.61)
  Top 0.254: 45.08,30.95 46.35,32.22 IC10.1 | 45.08,30.95 45.08,20.15 44.45,19.52 42.54,19.52 42.54,15.08 43.81,13.81 CORE-IO.13 | v48.26,45.55 45.08,42.38 45.08,30.95
  Bottom 0.254: v48.26,45.55 63.5,45.55 IC9.1
PIA-B1  (via drill 0.61)
  Top 0.254: v48.89,13.17 48.89,32.22 IC10.2 | v66.67,30.31 66.67,44.92 IC9.2
  Bottom 0.254: v48.89,13.17 46.98,13.17 CORE-IO.14 | v66.67,30.31 66.03,30.95 51.43,30.95 49.53,32.85 IC10.2
PIA-B2  (via drill 0.61)
  Top 0.254: v67.94,31.58 69.21,32.85 69.21,44.92 IC9.3 | v48.89,11.9 50.16,13.17 50.16,17.61 49.53,18.25 49.53,27.77 51.43,29.68 51.43,32.22 IC10.3
  Bottom 0.254: v67.94,31.58 53.34,31.58 52.07,32.85 IC10.3 | v48.89,11.9 45.72,11.9 44.45,10.63 CORE-IO.15
PIA-B3
  Bottom 0.254: IC17.1 53.34,12.54 51.43,10.63 46.98,10.63 CORE-IO.16
PIA-B4
  Bottom 0.254: IC17.2 55.88,12.54 52.7,9.36 45.72,9.36 44.45,8.09 CORE-IO.17
PIA-B5
  Bottom 0.254: IC17.3 58.41,12.54 53.97,8.09 46.98,8.09 CORE-IO.18
PIA-B6  (via drill 0.61)
  Top 0.254: 60.32,32.22 62.86,29.68 65.4,29.68 65.4,27.77 66.03,27.14 67.94,27.14 67.94,30.31 71.75,34.12 71.75,44.92 IC9.4 | 60.32,32.22 59.69,32.85 IC10.6 | v55.24,6.82 60.32,11.9 60.32,32.22
  Bottom 0.254: v55.24,6.82 45.72,6.82 44.45,5.55 CORE-IO.19
PIA-B7
  Top 0.254: JP1.17 76.19,25.87 74.92,27.14 70.48,27.14 70.48,19.52 64.77,13.81 IC17.5
  Bottom 0.254: IC17.5 63.5,12.54 56.51,5.55 46.98,5.55 CORE-IO.20
VCC  (via drill 0.61)
  Top 0.508: BYP8.1 52.07,79.21 53.34,79.21 IC8.20 53.97,77.94 55.24,76.67 55.24,69.05 53.97,67.78 IC7.20 53.97,65.24 55.24,63.97 55.24,23.33 53.97,22.06 IC17.16 53.97,19.52 52.7,18.25 52.7,7.46 54.61,5.55 66.03,5.55 66.03,12.54 IC17.6 | BYP12.1 87.62,28.41 88.89,28.41 IC12.20 | 88.26,15.71 88.89,15.71 IC11.20 | 88.26,15.71 87.62,15.71 BYP11.1 | 88.26,15.71 88.26,25.87 89.53,27.14 IC12.20 | BYP6.1 13.97,79.21 15.24,79.21 IC6.20 15.87,77.94 17.14,76.67 17.14,69.05 15.87,67.78 IC5.20 15.87,65.24 15.87,61.43 13.33,58.89 13.33,54.45 BYP4.1 | BYP1.1 13.33,16.34 13.33,21.42 15.87,23.96 15.87,27.14 IC2.20 | BYP3.1 13.33,41.74 13.33,46.82 15.87,49.37 15.87,52.54 IC4.20 | BYP2.1 13.33,29.04 13.33,31.58 14.6,32.85 14.6,36.66 15.87,37.94 15.87,39.84 IC3.20 16.5,41.74 v18.41,43.65 | IC11.11 112.39,16.98 111.12,18.25 111.12,25.87 112.39,27.14 IC12.11 112.39,29.68 112.39,30.95 111.12,32.22 111.12,38.57 112.39,39.84 IC13.11 112.39,42.38 111.75,43.02 111.75,44.28 111.12,44.92 111.12,51.27 112.39,52.54 IC14.11 112.39,55.08 111.12,56.35 111.12,63.97 112.39,65.24 IC15.11 112.39,67.78 112.39,68.41 111.12,69.69 111.12,76.67 112.39,77.94 IC16.11 | JP2.2 82.55,77.3 83.81,78.58 83.81,82.39 84.45,83.02 86.99,83.02 86.99,79.84 BYP16.1 87.62,79.21 88.89,79.21 IC16.20 89.53,77.94 88.26,76.67 88.26,66.51 | 88.26,66.51 88.89,66.51 IC15.20 89.53,65.24 88.26,63.97 88.26,53.81 | 88.26,66.51 87.62,66.51 BYP15.1 | 88.26,53.81 88.89,53.81 IC14.20 89.53,52.54 88.26,51.27 88.26,41.11 | 88.26,53.81 87.62,53.81 BYP14.1 | 88.26,41.11 88.89,41.11 IC13.20 | 88.26,41.11 87.62,41.11 BYP13.1
  Top 0.508: v60.32,39.2 60.32,51.91 61.59,53.17 BYP9.1 | 88.26,41.11 88.26,30.95 89.53,29.68 IC12.20
  Bottom 0.508: BYP7.1 52.07,66.51 53.34,66.51 IC7.20 | CORE-IO.11 44.45,15.71 45.72,15.71 CORE-IO.12 46.98,15.71 47.62,16.34 50.16,16.34 50.8,16.98 70.48,16.98 76.19,11.27 | BYP17.1 52.07,20.79 53.34,20.79 IC17.16 | 76.19,11.27 80.64,11.27 81.27,11.9 BYP18.1 82.55,11.9 86.35,15.71 BYP11.1 | 76.19,11.27 68.57,11.27 67.3,12.54 IC17.6 | BYP5.1 13.97,66.51 15.24,66.51 IC5.20 | BYP1.1 13.97,15.71 15.24,15.71 IC1.20 | BYP2.1 13.97,28.41 15.24,28.41 IC2.20 | BYP3.1 13.97,41.11 15.24,41.11 IC3.20 | BYP4.1 13.97,53.81 15.24,53.81 IC4.20 | BYP9.1 62.23,53.81 63.5,53.81 IC9.16 | BYP10.1 44.45,41.11 45.72,41.11 IC10.16 46.98,41.74 48.26,43.02 | 79.37,42.38 80.64,41.11 86.35,41.11 BYP13.1 | 79.37,42.38 76.83,44.92 IC9.6 | 60.32,43.02 66.67,43.02 67.3,42.38 79.37,42.38 | 48.26,43.02 60.32,43.02 | 60.32,43.02 v60.32,39.2 | IC15.11 111.75,67.14 110.48,68.41 91.44,68.41 90.16,67.14 IC15.20 | v18.41,43.65 19.04,43.02 48.26,43.02

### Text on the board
Top: PA8PDP/VRS | Component Side
Bottom: Solder Side
tValues: RealConsole I/O - Rev.1 | + | - | +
